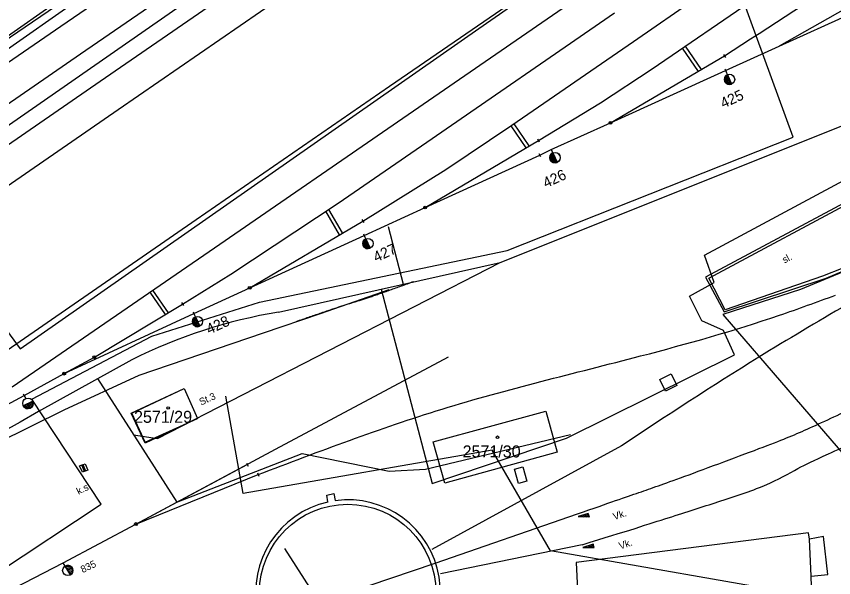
# Model space of a CAD drawing. Extents: x -469926 to -462499, y -1098642 to -1092733.
# Drawn here: x -465420 to -465304.2, y -1095542.9 to -1095463.4 of the extents above; entities that cross this region are included whole.
import ezdxf

# ---------------------------------------------------------------- set-up
doc = ezdxf.new("R2010")
doc.units = 0
for name, color, linetype in [('Vrstva 1', 7, 'Continuous'), ('Vrstva 2', 7, 'Continuous'), ('Vrstva 25', 7, 'Continuous'), ('Vrstva 4', 7, 'Continuous'), ('Vrstva 50', 7, 'Continuous'), ('Vrstva 51', 7, 'Continuous'), ('Vrstva 54', 7, 'Continuous'), ('Vrstva 55', 7, 'Continuous'), ('Vrstva 6', 7, 'Continuous'), ('Vrstva 62', 7, 'Continuous'), ('Vrstva 63', 7, 'Continuous'), ('Vrstva 8', 7, 'Continuous')]:
    doc.layers.add(name, color=color, linetype=linetype)

msp = doc.modelspace()

# ---------------------------------------------------------------- linework, layer by layer
at = {"layer": 'Vrstva 1'}
for p, q in [((-464930.08, -1095123.21), (-465604.79, -1095594.4)), ((-465332.58, -1095466.96), (-465306.94, -1095449.27)), ((-465329.91, -1095470.85), (-465304.39, -1095453.36)), ((-465367.13, -1095473.32), (-465340.47, -1095454.97)), ((-465405.59, -1095476.62), (-465381.25, -1095459.85)), ((-465364.52, -1095477.31), (-465337.9, -1095459)), ((-465311.91, -1095467.65), (-465294.82, -1095459.89)), ((-465299.25, -1095460.43), (-465311.91, -1095467.65)), ((-465361.84, -1095481.26), (-465335.24, -1095462.94)), ((-465349.82, -1095478.85), (-465332.58, -1095466.96)), ((-465335.82, -1095478.49), (-465319.67, -1095469.02)), ((-465335.82, -1095478.49), (-465319.67, -1095469.02)), ((-465337.26, -1095475.68), (-465329.91, -1095470.85)), ((-465394.53, -1095492.21), (-465367.13, -1095473.32)), ((-465346.05, -1095480.99), (-465337.26, -1095475.68)), ((-465428.91, -1095492.66), (-465405.59, -1095476.62)), ((-465391.95, -1095496.19), (-465364.52, -1095477.31)), ((-465344.21, -1095482.3), (-465335.82, -1095478.49)), ((-465359.18, -1095485.12), (-465349.82, -1095478.85)), ((-465374.42, -1095489.87), (-465361.84, -1095481.26)), ((-465362.08, -1095490.5), (-465346.05, -1095480.99)), ((-465362.08, -1095490.5), (-465345.86, -1095483.06)), ((-465362.08, -1095490.5), (-465345.86, -1095483.06)), ((-465345.86, -1095483.06), (-465344.21, -1095482.3)), ((-465370.91, -1095492.41), (-465359.18, -1095485.12)), ((-465389.64, -1095499.94), (-465374.42, -1095489.87)), ((-465370.73, -1095494.46), (-465362.08, -1095490.5)), ((-465419.47, -1095509.42), (-465394.53, -1095492.21)), ((-465386.95, -1095501.88), (-465370.91, -1095492.41)), ((-465386.95, -1095501.88), (-465370.73, -1095494.46)), ((-465386.95, -1095501.88), (-465370.73, -1095494.46)), ((-465420.63, -1095515.91), (-465391.95, -1095496.19)), ((-465296.74, -1095497.08), (-465308.89, -1095502.12)), ((-465396.47, -1095504.18), (-465389.64, -1095499.94)), ((-465394.87, -1095505.51), (-465386.95, -1095501.88)), ((-465308.89, -1095502.12), (-465319.9, -1095505.67)), ((-465408.97, -1095511.71), (-465396.47, -1095504.18)), ((-465408.97, -1095511.71), (-465396.47, -1095504.18)), ((-465413.23, -1095514.02), (-465394.87, -1095505.51)), ((-465384.98, -1095508.24), (-465376.9, -1095505.5)), ((-465319.9, -1095505.67), (-465298.28, -1095530.74)), ((-465402.61, -1095514.24), (-465384.98, -1095508.24)), ((-465402.61, -1095514.24), (-465384.98, -1095508.24)), ((-465444.1, -1095526.44), (-465419.47, -1095509.42)), ((-465418.92, -1095517.11), (-465413.23, -1095514.02)), ((-465413.24, -1095519.16), (-465402.61, -1095514.24)), ((-465403.73, -1095519.61), (-465396.25, -1095516.14)), ((-465396.25, -1095516.14), (-465394.33, -1095520.39)), ((-465435.33, -1095526.02), (-465418.92, -1095517.11)), ((-465435.33, -1095526.02), (-465418.92, -1095517.11)), ((-465443.28, -1095533.89), (-465413.24, -1095519.16)), ((-465401.75, -1095523.88), (-465403.73, -1095519.61)), ((-465360.95, -1095523.7), (-465345.01, -1095519.34)), ((-465345.01, -1095519.34), (-465343.39, -1095525.14)), ((-465394.33, -1095520.39), (-465401.75, -1095523.88)), ((-465359.31, -1095529.53), (-465360.95, -1095523.7)), ((-465343.39, -1095525.14), (-465359.31, -1095529.53)), ((-465307.75, -1095536.59), (-465340.69, -1095540.75)), ((-465307.62, -1095537.47), (-465307.75, -1095536.59)), ((-465305.66, -1095537.09), (-465307.62, -1095537.47)), ((-465305.02, -1095542.45), (-465305.66, -1095537.09)), ((-465340.69, -1095540.75), (-465340.41, -1095546.94)), ((-465307.38, -1095542.69), (-465305.02, -1095542.45)), ((-465307.21, -1095549.17), (-465307.38, -1095542.69))]:
    msp.add_line(p, q, dxfattribs=at)
for points in [[(-465463.01, -1095499.1), (-465435.56, -1095479.77), (-465413.73, -1095464.8), (-465388.44, -1095447.47), (-465359.6, -1095427.66), (-465331.96, -1095408.63), (-465320.6, -1095400.8)], [(-465460.28, -1095503.23), (-465432.66, -1095483.69), (-465410.93, -1095468.72), (-465385.78, -1095451.43), (-465356.89, -1095431.55), (-465329.34, -1095412.58), (-465317.88, -1095404.67)], [(-465457.37, -1095506.97), (-465429.89, -1095487.57), (-465408.14, -1095472.6), (-465383.28, -1095455.47), (-465353.88, -1095435.18), (-465326.36, -1095416.22), (-465315.19, -1095408.52)], [(-465335.82, -1095478.49), (-465319.51, -1095471.08), (-465311.91, -1095467.65)], [(-465403.07, -1095535.32), (-465383.3, -1095524.72), (-465358.76, -1095511.64)], [(-465334.26, -1095524.23), (-465361.16, -1095538.95)], [(-465413.39, -1095540.84), (-465403.07, -1095535.32), (-465387.31, -1095526.89)], [(-465427.21, -1095547.97), (-465413.39, -1095540.84), (-465403.07, -1095535.32), (-465385.75, -1095528.32)], [(-465424.4, -1095563.16), (-465385.37, -1095549.21), (-465360.69, -1095540.86), (-465340.52, -1095533.9)], [(-465339.85, -1095538.25), (-465359.91, -1095542.36)]]:
    msp.add_lwpolyline(points, dxfattribs=at)
for points in [[(-465319.69, -1095469.01), (-465300, -1095456.21), (-465260.4, -1095428.96)], [(-465385.75, -1095528.32), (-465359.7, -1095519.05), (-465331.56, -1095511.52), (-465311.89, -1095505.75), (-465303.92, -1095502.9)], [(-465302.38, -1095504.27), (-465314.82, -1095511.7), (-465334.26, -1095524.23)]]:
    msp.add_spline(points, degree=3, dxfattribs=at)
for points, degree in [([(-465339.85, -1095538.25), (-465333.48, -1095536.31), (-465327.1, -1095534.27), (-465320.73, -1095532.22), (-465313.54, -1095529.91), (-465309, -1095527.24), (-465306.22, -1095525.98), (-465295.64, -1095521.1), (-465293.79, -1095520.2), (-465283.25, -1095514.79), (-465279.76, -1095512.76), (-465276.4, -1095510.57), (-465273.06, -1095508.32), (-465271.3, -1095507.13), (-465269.54, -1095505.94), (-465267.77, -1095504.75), (-465266.6, -1095503.96), (-465254.39, -1095495.56), (-465231.15, -1095479.54)], 3), ([(-465340.52, -1095533.9), (-465335.85, -1095532.27), (-465331.42, -1095530.73), (-465326.99, -1095529.2), (-465312.49, -1095523.81), (-465308.23, -1095522.07), (-465300, -1095518.18), (-465297.65, -1095517.12), (-465295.8, -1095516.21), (-465291.34, -1095513.75), (-465285.4, -1095510.23), (-465279.47, -1095506.7), (-465273.54, -1095503.18), (-465269.58, -1095500.83), (-465262.38, -1095495.93), (-465251.93, -1095488.49)], 3), ([(-465380.34, -1095506.63), (-465374.81, -1095504.7), (-465369.19, -1095502.97), (-465363.69, -1095500.96)], 2)]:
    msp.add_open_spline(points, degree=degree, dxfattribs=at)
at = {"layer": 'Vrstva 25'}
for centre in [(-465398.51, -1095518.88), (-465351.84, -1095523.03)]:
    msp.add_circle(centre, 0.175, dxfattribs=at)
at = {"layer": 'Vrstva 4'}
msp.add_line((-465307.38, -1095542.69), (-465307.62, -1095537.47), dxfattribs=at)
at = {"layer": 'Vrstva 50'}
for p, q in [((-465458.64, -1095494.18), (-465408.86, -1095459.35)), ((-465309.93, -1095480.54), (-465317.46, -1095459.89)), ((-465350.46, -1095496.56), (-465309.93, -1095480.54)), ((-465385.58, -1095503.9), (-465350.46, -1095496.56)), ((-465400.82, -1095508.73), (-465385.58, -1095503.9)), ((-465417.82, -1095517.62), (-465400.82, -1095508.73)), ((-465408.02, -1095532.52), (-465417.82, -1095517.62)), ((-465439.37, -1095553.29), (-465408.02, -1095532.52))]:
    msp.add_line(p, q, dxfattribs=at)
at = {"layer": 'Vrstva 51'}
for p, q in [((-465354.49, -1095465.13), (-465210.59, -1095364.95)), ((-465427.33, -1095483.12), (-465387.28, -1095455.27)), ((-465419.47, -1095510.52), (-465354.49, -1095465.13)), ((-465351.48, -1095498.29), (-465291.1, -1095474.15)), ((-465322.5, -1095497.24), (-465289.03, -1095479.25)), ((-465367.31, -1095493.16), (-465365.2, -1095501.36)), ((-465400.02, -1095523.2), (-465351.48, -1095498.29)), ((-465382.85, -1095505.32), (-465351.48, -1095498.29)), ((-465321.14, -1095501.12), (-465322.5, -1095497.24)), ((-465427.38, -1095499.83), (-465419.47, -1095510.52)), ((-465324.63, -1095503.05), (-465321.14, -1095501.12)), ((-465368.32, -1095502.06), (-465361.12, -1095529.56)), ((-465322.89, -1095506.54), (-465324.63, -1095503.05)), ((-465319.79, -1095507.9), (-465322.89, -1095506.54)), ((-465318.24, -1095511.38), (-465319.79, -1095507.9)), ((-465342.04, -1095523.15), (-465318.24, -1095511.38)), ((-465408.52, -1095514.71), (-465397.3, -1095532.22)), ((-465403.42, -1095522.67), (-465400.02, -1095523.2)), ((-465362.02, -1095527.57), (-465341.51, -1095522.64)), ((-465361.12, -1095529.56), (-465342.04, -1095523.15)), ((-465397.3, -1095532.22), (-465379.53, -1095525.34)), ((-465379.53, -1095525.34), (-465367.21, -1095527.84)), ((-465367.21, -1095527.84), (-465362.02, -1095527.57)), ((-465363.39, -1095567.51), (-465381.99, -1095538.78))]:
    msp.add_line(p, q, dxfattribs=at)
for centre, radius, start, end in [((-465370.68, -1095578.35), 74.05, 99.4618, 116.4618), ((-464905.76, -1096424.95), 1039.84, 118.60916, 123.93467)]:
    msp.add_arc(centre, radius, start, end, dxfattribs=at)
at = {"layer": 'Vrstva 54'}
msp.add_lwpolyline([(-464916.82, -1095124.42), (-464935.66, -1095137.37), (-465026.27, -1095189.19), (-465020.81, -1095196.55), (-465298.4, -1095387.38), (-465300.51, -1095384.31), (-465702.28, -1095658.07)], dxfattribs=at)
at = {"layer": 'Vrstva 55'}
for p, q in [((-465344.03, -1095482.77), (-465344.37, -1095483.66)), ((-465343.89, -1095482.94), (-465344.24, -1095483.87)), ((-465343.98, -1095482.74), (-465344.2, -1095482.28)), ((-465343.78, -1095483.18), (-465344.1, -1095484.01)), ((-465343.98, -1095482.74), (-465343.38, -1095484.08)), ((-465343.98, -1095482.74), (-465343.98, -1095482.74)), ((-465343.38, -1095484.08), (-465343.98, -1095482.74)), ((-465343.67, -1095483.42), (-465343.93, -1095484.1)), ((-465343.57, -1095483.66), (-465343.74, -1095484.14)), ((-465343.46, -1095483.9), (-465343.54, -1095484.13)), ((-465387.43, -1095526.68), (-465387.19, -1095527.11)), ((-465387.31, -1095526.89), (-465387.31, -1095526.89)), ((-465410.53, -1095527.43), (-465410.53, -1095527.43)), ((-465403.07, -1095535.32), (-465385.75, -1095528.32)), ((-465385.85, -1095528.09), (-465385.64, -1095528.54)), ((-465385.75, -1095528.32), (-465385.75, -1095528.32)), ((-465340.52, -1095533.9), (-465340.52, -1095533.9)), ((-465339.98, -1095534.15), (-465339.71, -1095534.3)), ((-465339.73, -1095534.07), (-465339.29, -1095534.31)), ((-465339.48, -1095534), (-465338.88, -1095534.31)), ((-465339.23, -1095533.92), (-465338.89, -1095534.1)), ((-465338.97, -1095533.84), (-465338.97, -1095533.84)), ((-465340.24, -1095534.23), (-465340.13, -1095534.29)), ((-465339.85, -1095538.25), (-465339.85, -1095538.25)), ((-465339.57, -1095538.58), (-465339.46, -1095538.64)), ((-465339.32, -1095538.5), (-465339.04, -1095538.65)), ((-465339.06, -1095538.43), (-465338.62, -1095538.66)), ((-465338.81, -1095538.35), (-465338.21, -1095538.67)), ((-465338.55, -1095538.27), (-465338.22, -1095538.45)), ((-465338.3, -1095538.19), (-465338.29, -1095538.2)), ((-465413.12, -1095541.28), (-465413.39, -1095540.84)), ((-465413.12, -1095541.28), (-465412.34, -1095542.51)), ((-465413.12, -1095541.28), (-465413.12, -1095541.28)), ((-465412.34, -1095542.51), (-465413.12, -1095541.28)), ((-465413.07, -1095541.25), (-465412.14, -1095541.46)), ((-465413.01, -1095541.46), (-465412.03, -1095541.68)), ((-465412.86, -1095541.68), (-465412, -1095541.88)), ((-465412.72, -1095541.91), (-465412.02, -1095542.06)), ((-465412.58, -1095542.13), (-465412.09, -1095542.24)), ((-465412.44, -1095542.35), (-465412.21, -1095542.41))]:
    msp.add_line(p, q, dxfattribs=at)
for points in [[(-465300, -1095488.4), (-465322.35, -1095500.37), (-465319.72, -1095505.29), (-465305.25, -1095500.51), (-465300, -1095498.26)], [(-465300, -1095497.96), (-465305.77, -1095500.21), (-465319.57, -1095504.97), (-465321.89, -1095500.52), (-465300, -1095488.78)], [(-465328.85, -1095514.83), (-465327.23, -1095514.03), (-465326.44, -1095515.72), (-465328.03, -1095516.51), (-465328.85, -1095514.83)], [(-465410.73, -1095526.97), (-465410.27, -1095526.78), (-465409.88, -1095527.7), (-465410.34, -1095527.89), (-465410.73, -1095526.97)], [(-465349.45, -1095527.57), (-465348.25, -1095527.22), (-465347.67, -1095529.23), (-465348.87, -1095529.57), (-465349.45, -1095527.57)], [(-465375.88, -1095532.2), (-465376.01, -1095531.22), (-465375.03, -1095531.02), (-465374.85, -1095532.01)], [(-465340.4, -1095534.28), (-465338.82, -1095534.32), (-465338.97, -1095533.84), (-465340.4, -1095534.28)], [(-465340.4, -1095534.28), (-465338.82, -1095534.32), (-465338.97, -1095533.84), (-465340.4, -1095534.28)], [(-465339.73, -1095538.63), (-465338.15, -1095538.67), (-465338.29, -1095538.19), (-465339.73, -1095538.63)], [(-465339.73, -1095538.63), (-465338.15, -1095538.67), (-465338.29, -1095538.19), (-465339.73, -1095538.63)]]:
    msp.add_lwpolyline(points, dxfattribs=at)
for centre, radius in [((-465343.68, -1095483.41), 0.731), ((-465373.07, -1095545.02), 12.5), ((-465403.07, -1095535.32), 0.2), ((-465412.73, -1095541.9), 0.731)]:
    msp.add_circle(centre, radius, dxfattribs=at)
for centre, radius, start, end in [((-465343.68, -1095483.41), 0.732, 114.437, 294.3978), ((-465373.02, -1095544.96), 13.07, 102.6419, 98.0562), ((-465412.73, -1095541.9), 0.732, 302.3052, 122.2661)]:
    msp.add_arc(centre, radius, start, end, dxfattribs=at)
at = {"layer": 'Vrstva 6'}
for p, q in [((-465344.21, -1095482.3), (-465335.82, -1095478.49)), ((-465362.08, -1095490.5), (-465346.05, -1095480.99)), ((-465370.73, -1095494.46), (-465362.08, -1095490.5)), ((-465386.95, -1095501.88), (-465370.91, -1095492.41)), ((-465394.87, -1095505.51), (-465386.95, -1095501.88)), ((-465376.9, -1095505.5), (-465367.17, -1095502.11)), ((-465413.23, -1095514.02), (-465394.87, -1095505.51)), ((-465413.23, -1095514.02), (-465408.97, -1095511.71)), ((-465418.92, -1095517.11), (-465413.23, -1095514.02)), ((-465413.24, -1095519.16), (-465402.61, -1095514.24)), ((-465403.67, -1095519.61), (-465396.23, -1095516.15)), ((-465396.23, -1095516.15), (-465394.33, -1095520.39)), ((-465401.76, -1095523.72), (-465403.67, -1095519.61)), ((-465401.76, -1095523.72), (-465394.33, -1095520.39))]:
    msp.add_line(p, q, dxfattribs=at)
at = {"layer": 'Vrstva 62'}
for p, q in [((-465325.67, -1095467.94), (-465323.42, -1095471.22)), ((-465325.25, -1095467.66), (-465322.99, -1095470.96)), ((-465349.95, -1095478.93), (-465347.81, -1095482.03)), ((-465349.53, -1095478.65), (-465347.38, -1095481.78)), ((-465374.21, -1095494.36), (-465376.18, -1095491.03)), ((-465373.78, -1095494.1), (-465375.76, -1095490.76)), ((-465401.12, -1095502.49), (-465398.94, -1095505.67)), ((-465400.71, -1095502.21), (-465398.51, -1095505.41))]:
    msp.add_line(p, q, dxfattribs=at)
at = {"layer": 'Vrstva 63'}
for p, q in [((-465387.9, -1095531.02), (-465390.33, -1095517.22)), ((-465352.58, -1095524.85), (-465387.9, -1095531.02)), ((-465344.35, -1095539.13), (-465352.58, -1095524.85)), ((-465305.38, -1095545.9), (-465344.35, -1095539.13))]:
    msp.add_line(p, q, dxfattribs=at)
at = {"layer": 'Vrstva 8'}
for p, q in [((-465319.8, -1095468.8), (-465319.55, -1095469.24)), ((-465319.61, -1095470.85), (-465319.41, -1095471.31)), ((-465319.26, -1095471.67), (-465319.48, -1095471.2)), ((-465319.26, -1095471.67), (-465318.66, -1095473)), ((-465319.26, -1095471.67), (-465319.26, -1095471.67)), ((-465318.66, -1095473), (-465319.26, -1095471.67)), ((-465319.31, -1095471.7), (-465319.64, -1095472.59)), ((-465319.17, -1095471.86), (-465319.52, -1095472.8)), ((-465319.06, -1095472.11), (-465319.38, -1095472.94)), ((-465318.95, -1095472.35), (-465319.21, -1095473.02)), ((-465318.85, -1095472.59), (-465319.02, -1095473.06)), ((-465318.73, -1095472.83), (-465318.82, -1095473.05)), ((-465346.18, -1095480.78), (-465345.92, -1095481.21)), ((-465345.96, -1095482.83), (-465345.76, -1095483.29)), ((-465344.04, -1095482.79), (-465344.38, -1095483.68)), ((-465343.91, -1095482.96), (-465344.26, -1095483.89)), ((-465343.99, -1095482.76), (-465344.21, -1095482.3)), ((-465343.8, -1095483.2), (-465344.11, -1095484.03)), ((-465343.99, -1095482.77), (-465343.39, -1095484.1)), ((-465343.99, -1095482.77), (-465343.99, -1095482.77)), ((-465343.39, -1095484.1), (-465343.99, -1095482.77)), ((-465343.69, -1095483.44), (-465343.94, -1095484.12)), ((-465343.58, -1095483.68), (-465343.76, -1095484.16)), ((-465343.47, -1095483.92), (-465343.55, -1095484.15)), ((-465371.04, -1095492.19), (-465370.78, -1095492.62)), ((-465370.83, -1095494.23), (-465370.62, -1095494.69)), ((-465370.51, -1095494.93), (-465370.73, -1095494.46)), ((-465370.56, -1095494.96), (-465370.89, -1095495.84)), ((-465370.42, -1095495.12), (-465370.77, -1095496.06)), ((-465370.31, -1095495.36), (-465370.62, -1095496.2)), ((-465370.51, -1095494.93), (-465369.9, -1095496.26)), ((-465370.51, -1095494.93), (-465370.51, -1095494.93)), ((-465369.9, -1095496.26), (-465370.51, -1095494.93)), ((-465370.2, -1095495.6), (-465370.45, -1095496.28)), ((-465370.09, -1095495.84), (-465370.27, -1095496.32)), ((-465369.98, -1095496.09), (-465370.06, -1095496.31)), ((-465396.6, -1095503.97), (-465396.34, -1095504.39)), ((-465394.7, -1095506), (-465395.03, -1095506.89)), ((-465394.97, -1095505.28), (-465394.76, -1095505.74)), ((-465394.57, -1095506.17), (-465394.91, -1095507.1)), ((-465394.65, -1095505.98), (-465394.87, -1095505.51)), ((-465394.46, -1095506.41), (-465394.77, -1095507.24)), ((-465394.65, -1095505.98), (-465394.04, -1095507.31)), ((-465394.65, -1095505.98), (-465394.65, -1095505.98)), ((-465394.04, -1095507.31), (-465394.65, -1095505.98)), ((-465394.35, -1095506.65), (-465394.6, -1095507.33)), ((-465394.23, -1095506.89), (-465394.41, -1095507.37)), ((-465394.12, -1095507.13), (-465394.21, -1095507.36)), ((-465413.23, -1095514.02), (-465408.97, -1095511.71)), ((-465417.7, -1095517.91), (-465419.05, -1095518.56)), ((-465419.05, -1095518.56), (-465417.7, -1095517.91)), ((-465419.04, -1095516.89), (-465418.8, -1095517.33)), ((-465418.92, -1095517.11), (-465418.7, -1095517.56)), ((-465418.19, -1095518.96), (-465417.85, -1095517.98)), ((-465418.95, -1095518.71), (-465418.87, -1095518.48)), ((-465418.79, -1095518.85), (-465418.62, -1095518.35)), ((-465418.61, -1095518.94), (-465418.36, -1095518.23)), ((-465418.41, -1095518.98), (-465418.11, -1095518.11)), ((-465417.94, -1095518.85), (-465417.66, -1095518.02))]:
    msp.add_line(p, q, dxfattribs=at)
msp.add_lwpolyline([(-465410.2, -1095527.8), (-465410.65, -1095528), (-465411.06, -1095527.09), (-465410.6, -1095526.88), (-465410.2, -1095527.8)], dxfattribs=at)
for centre, radius in [((-465318.96, -1095472.34), 0.731), ((-465335.82, -1095478.49), 0.2), ((-465343.69, -1095483.44), 0.731), ((-465362.08, -1095490.5), 0.2), ((-465370.2, -1095495.6), 0.731), ((-465386.95, -1095501.88), 0.2), ((-465394.35, -1095506.64), 0.731), ((-465408.97, -1095511.71), 0.2), ((-465413.23, -1095514.02), 0.2), ((-465418.37, -1095518.23), 0.75)]:
    msp.add_circle(centre, radius, dxfattribs=at)
for centre, radius, start, end in [((-465318.96, -1095472.34), 0.732, 114.4492, 294.41), ((-465343.69, -1095483.43), 0.732, 114.4492, 294.41), ((-465370.21, -1095495.59), 0.732, 114.66, 294.6209), ((-465394.35, -1095506.64), 0.732, 114.6068, 294.5676), ((-465418.37, -1095518.23), 0.75, 205.8558, 25.8558)]:
    msp.add_arc(centre, radius, start, end, dxfattribs=at)

# ---------------------------------------------------------------- texts
at = {"layer": 'Vrstva 2'}
for s, p in [('425', (-465319.84, -1095476.49)), ('426', (-465344.98, -1095487.77)), ('427', (-465369.03, -1095498.28)), ('428', (-465392.69, -1095508.5))]:
    msp.add_text(s, height=1.5, rotation=24.7188, dxfattribs=at).set_placement(p)
at = {"layer": 'Vrstva 50'}
for s, p in [('2571/29', (-465403.34, -1095520.99)), ('2571/30', (-465356.78, -1095525.89))]:
    msp.add_text(s, height=1.7, dxfattribs=at).set_placement(p)
at = {"layer": 'Vrstva 55'}
for s, rotation, p in [('sl.', 28.1694, (-465311.17, -1095498.43)), ('St.3', 24.4861, (-465393.84, -1095518.55)), ('k.s.', 27.1576, (-465411.19, -1095531.2)), ('Vk.', 18.0375, (-465335.29, -1095534.77)), ('Vk.', 17.8304, (-465334.46, -1095538.93)), ('835', 25.5144, (-465410.62, -1095542.28))]:
    msp.add_text(s, height=1, rotation=rotation, dxfattribs=at).set_placement(p)

doc.saveas('drawing.dxf')
